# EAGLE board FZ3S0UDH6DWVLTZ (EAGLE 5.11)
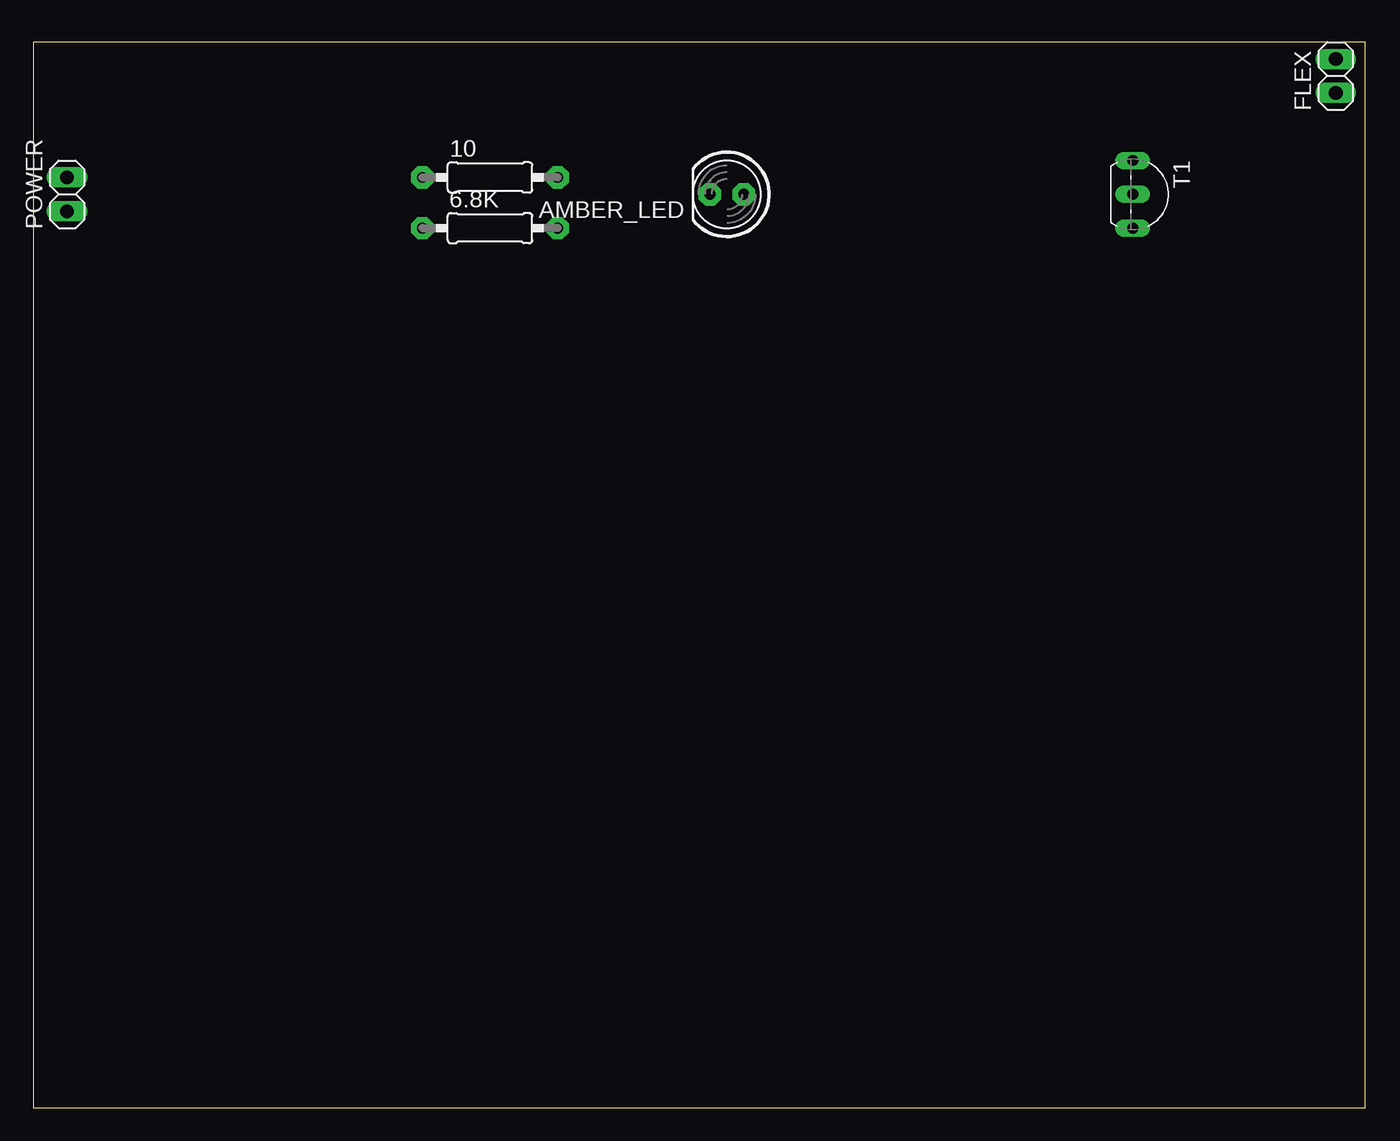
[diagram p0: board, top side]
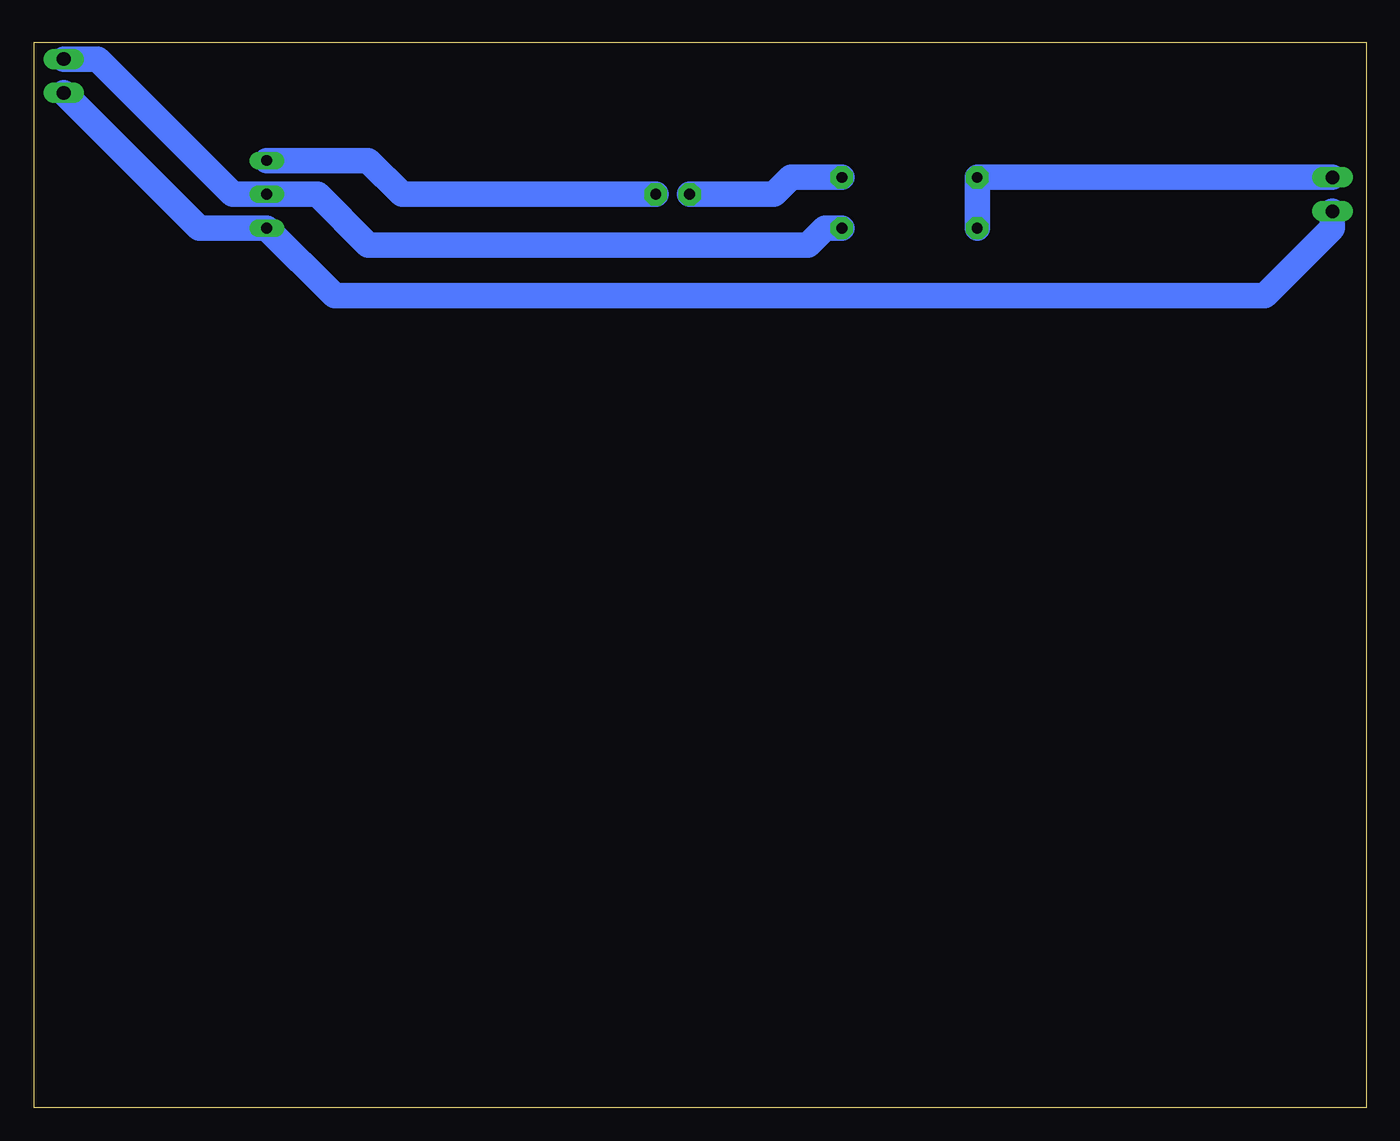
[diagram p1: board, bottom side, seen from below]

Size 100 x 80 mm. Coordinates in mm from the lower left corner, seen from the top.
Outline: 0,0 100,0 100,80 0,80 0,0
Copper layers (1*16): Top 0.035mm / dielectric 1.5mm / Bottom 0.035mm
Design rules "default": minimum track width 10mil, minimum drill 24mil, track to track 8mil, track to pad 8mil, pad to pad 8mil, via to via 8mil, smd to smd 8mil, copper to edge 40mil, drill to drill 8mil, minimum pad ring 10mil, minimum via ring 8mil, stop-mask expansion 4mil, vias tented up to drill 0mil, thermal gap 10mil

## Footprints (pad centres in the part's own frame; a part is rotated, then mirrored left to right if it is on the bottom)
0207/10 = drill 0.813 pad 1.676 octagon: 1 -5.08,0; 2 5.08,0
LED5MM = drill 0.813 pad 1.676 octagon: A -1.27,0; K 1.27,0
1X02 = drill 1.016 long: 1 -1.27,0; 2 1.27,0
TO92-EBC-OVAL = drill 0.813 long: B 0,-1.27; C 2.54,-1.27; E -2.54,-1.27

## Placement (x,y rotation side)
6.8K  [0207/10]  34.29,66.04 0 top
10  [0207/10]  34.29,69.85 0 top
AMBER_LED  [LED5MM]  52.07,68.58 180 top
FLEX  [1X02]  97.79,77.47 90 top
POWER  [1X02]  2.54,68.58 90 top
T1  2N2222  [TO92-EBC-OVAL]  83.82,68.58 270 top

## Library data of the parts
6.8K 10 AMBER_LED T1 = adafruit
FLEX POWER = pinhead

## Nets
N$1: FLEX.1 POWER.1 T1.C
N$2: AMBER_LED.A T1.E
N$3: 10.2 AMBER_LED.K
N$4: 6.8K.1 10.1 POWER.2
N$5: 6.8K.2 FLEX.2 T1.B

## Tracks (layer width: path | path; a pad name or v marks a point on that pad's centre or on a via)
N$1
  Bottom 1.93: POWER.1 2.54,66.04 7.62,60.96 77.47,60.96 T1.C 87.63,66.04 FLEX.1
N$2
  Bottom 1.93: T1.E 74.93,71.12 72.39,68.58 AMBER_LED.A
N$3
  Bottom 1.93: 10.2 41.91,69.85 43.18,69.85 44.45,68.58 AMBER_LED.K
N$4
  Bottom 1.93: 6.8K.1 29.21,68.58 10.1 POWER.2
N$5
  Bottom 1.93: FLEX.2 95.25,78.74 85.09,68.58 T1.B 78.74,68.58 74.93,64.77 41.91,64.77 40.64,66.04 6.8K.2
